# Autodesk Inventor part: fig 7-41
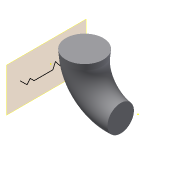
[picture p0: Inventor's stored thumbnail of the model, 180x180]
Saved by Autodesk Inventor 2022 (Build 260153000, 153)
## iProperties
Created: 2011-07
Part Number: fig 7-41
Material: Generic
Document SubType Name: Modeling
Designer: CadCim
Density: 1 g/cm^3
Appearance: Default
Author: CadCim
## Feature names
1. Sweep1
## Parameters: d0 = 5 deg, d1 = -14.75 mm, d2 = 0
